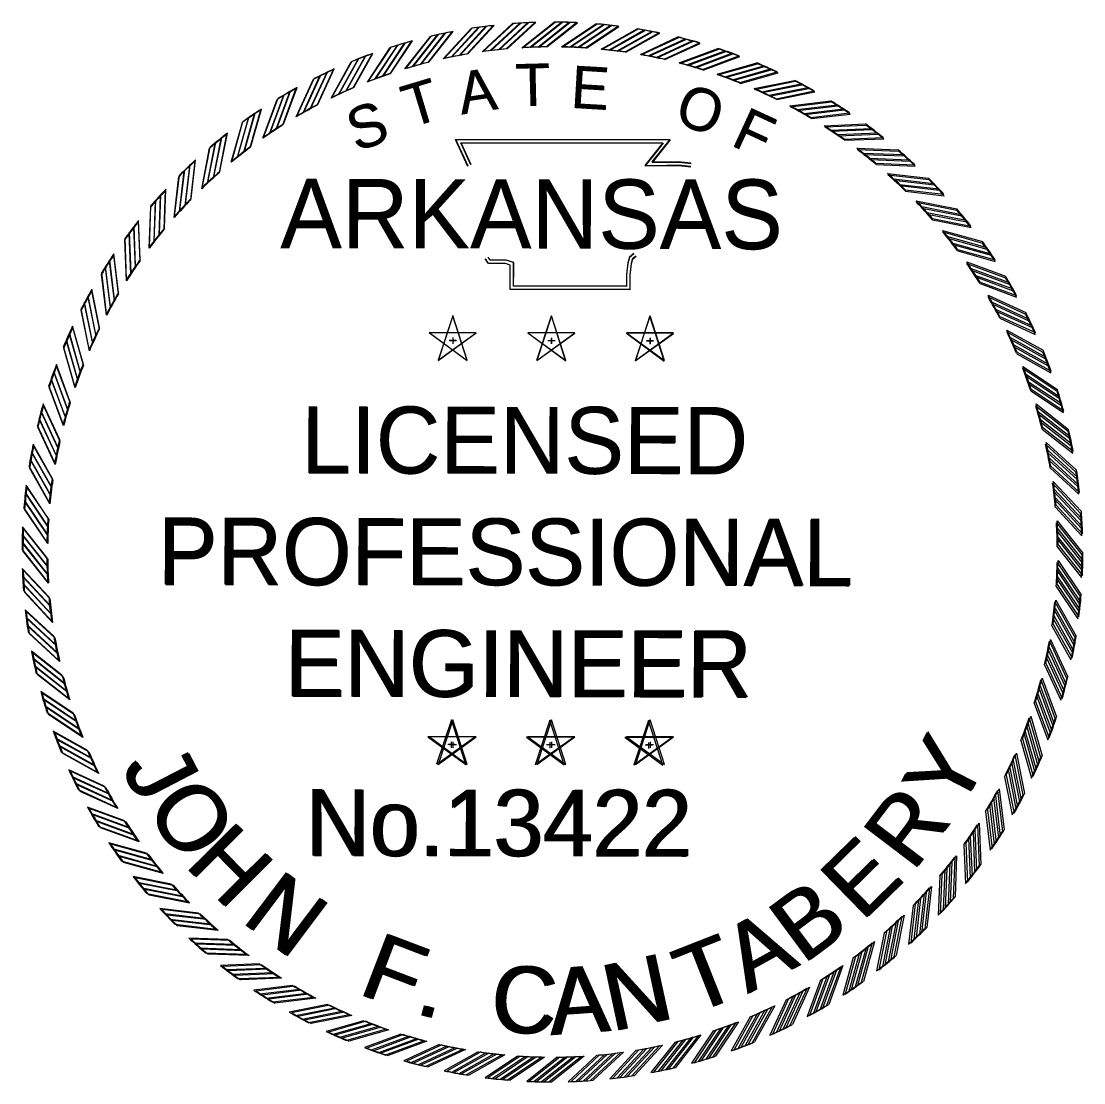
# Model space of a CAD drawing. Extents: x 1373884 to 1376992, y 1168426 to 1170473.
# Drawn here: x 1376555.8 to 1376796.3, y 1168433.2 to 1168673.5 of the extents above; entities that cross this region are included whole.
import ezdxf

# ---------------------------------------------------------------- set-up
doc = ezdxf.new("R2010")
doc.units = 0
doc.layers.add('Default', color=7, linetype='Continuous')
doc.layers.add('G-ANNO-STMP', color=7, linetype='Continuous')

# ---------------------------------------------------------------- blocks, each defined once
blk = doc.blocks.new('STAR')
at = {"layer": 'Default'}
for p, q in [((-0.0001, 0.0615), (-0.0366, -0.0504)), ((0.0362, -0.0503), (0, 0.0617)), ((0.0587, 0.0188), (-0.059, 0.0189)), ((-0.0589, 0.0188), (0.0363, -0.0505)), ((-0.0365, -0.0503), (0.0589, 0.0188)), ((-0.0085, 0), (0.009, 0)), ((0, 0.0063), (0, -0.0085))]:
    blk.add_line(p, q, dxfattribs=at)
blk = doc.blocks.new('RP')
at = {"layer": 'Default'}
for p, q in [((-0.0781, 1.2656), (0.003, 1.33)), ((-0.058, 1.2667), (0.0216, 1.3299)), ((-0.0375, 1.2674), (0.0405, 1.3294)), ((-0.0176, 1.2679), (0.059, 1.3287))]:
    blk.add_line(p, q, dxfattribs=at)
for radius, start, end in [(1.33, 87.4562, 89.8699), (1.268, 90.7933, 93.5307)]:
    blk.add_arc((0, 0), radius, start, end, dxfattribs=at)

msp = doc.modelspace()

# ---------------------------------------------------------------- linework, layer by layer
at = {"layer": 'G-ANNO-STMP'}
for points in [[(1376656.89, 1168640.66), (1376654.09, 1168646.73), (1376702.61, 1168646.76), (1376698.55, 1168641.66), (1376701.85, 1168641.71), (1376704.6, 1168641.74), (1376707.35, 1168641.44)], [(1376656.99, 1168640.69), (1376654.2, 1168646.77), (1376702.72, 1168646.63), (1376698.65, 1168641.55), (1376701.95, 1168641.59), (1376704.7, 1168641.61), (1376707.45, 1168641.3)], [(1376657.59, 1168640.98), (1376655.29, 1168645.96), (1376701.01, 1168645.99), (1376696.94, 1168640.87), (1376701.86, 1168640.94), (1376704.57, 1168640.97), (1376707.27, 1168640.68)], [(1376657.69, 1168641.01), (1376655.4, 1168646), (1376701.13, 1168645.87), (1376697.04, 1168640.77), (1376701.95, 1168640.82), (1376704.66, 1168640.84), (1376707.37, 1168640.54)], [(1376694.48, 1168620.92), (1376693.46, 1168620.09), (1376693.1, 1168618.79), (1376692.82, 1168616.17), (1376692.82, 1168613.54), (1376667.27, 1168613.54), (1376667.27, 1168617.3), (1376667.27, 1168618.88), (1376665.52, 1168619.41), (1376661.96, 1168619.41), (1376661.51, 1168620.11)], [(1376694.5, 1168620.82), (1376693.48, 1168620), (1376693.12, 1168618.7), (1376692.83, 1168616.08), (1376692.82, 1168613.45), (1376667.27, 1168613.54), (1376667.28, 1168617.3), (1376667.29, 1168618.87), (1376665.54, 1168619.42), (1376661.99, 1168619.43), (1376661.53, 1168620.13)], [(1376694.96, 1168620.32), (1376694.13, 1168619.65), (1376693.86, 1168618.64), (1376693.58, 1168616.13), (1376693.58, 1168612.77), (1376666.5, 1168612.77), (1376666.5, 1168617.3), (1376666.5, 1168618.31), (1376665.4, 1168618.64), (1376661.55, 1168618.64), (1376660.86, 1168619.69)], [(1376694.99, 1168620.23), (1376694.16, 1168619.56), (1376693.88, 1168618.55), (1376693.6, 1168616.04), (1376693.58, 1168612.68), (1376666.5, 1168612.77), (1376666.51, 1168617.3), (1376666.52, 1168618.31), (1376665.42, 1168618.65), (1376661.57, 1168618.66), (1376660.89, 1168619.71)]]:
    msp.add_lwpolyline(points, dxfattribs=at)

# ---------------------------------------------------------------- block references
for name, p, xscale, yscale, rotation in [('RP', (1376676.16, 1168553.35), 90.20715837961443, 90.20715837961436, 4.500000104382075), ('RP', (1376675.96, 1168553.32), 90.2071583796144, 90.20715837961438, 4.304199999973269), ('RP', (1376676.16, 1168553.35), 90.2071583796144, 90.20715837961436, 1.0438208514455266e-07), ('RP', (1376676.16, 1168553.35), 90.20715837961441, 90.20715837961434, -4.499999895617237), ('RP', (1376675.96, 1168553.32), 90.20715837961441, 90.20715837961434, -4.695800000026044), ('RP', (1376676.16, 1168553.35), 90.20715837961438, 90.20715837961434, 13.500000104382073), ('RP', (1376675.96, 1168553.32), 90.2071583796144, 90.20715837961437, 13.304199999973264), ('RP', (1376676.16, 1168553.35), 90.20715837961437, 90.20715837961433, 9.000000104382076), ('RP', (1376675.96, 1168553.32), 90.20715837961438, 90.20715837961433, 8.804199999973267), ('RP', (1376675.96, 1168553.32), 90.2071583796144, 90.20715837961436, -0.19580000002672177), ('RP', (1376676.16, 1168553.35), 90.20715837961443, 90.20715837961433, -8.999999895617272), ('RP', (1376675.96, 1168553.32), 90.20715837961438, 90.20715837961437, -9.19580000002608), ('RP', (1376676.16, 1168553.35), 90.20715837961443, 90.20715837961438, -13.499999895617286), ('RP', (1376675.96, 1168553.32), 90.20715837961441, 90.20715837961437, -13.695800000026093), ('RP', (1376676.16, 1168553.35), 90.20715837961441, 90.20715837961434, 18.00000010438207), ('RP', (1376675.96, 1168553.32), 90.2071583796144, 90.20715837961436, 17.804199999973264), ('RP', (1376676.16, 1168553.35), 90.20715837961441, 90.20715837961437, -17.999999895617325), ('RP', (1376675.96, 1168553.32), 90.2071583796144, 90.20715837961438, -18.19580000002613), ('RP', (1376676.16, 1168553.35), 90.2071583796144, 90.20715837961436, 22.500000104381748), ('RP', (1376675.96, 1168553.32), 90.2071583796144, 90.20715837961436, 22.304199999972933), ('RP', (1376676.16, 1168553.35), 90.20715837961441, 90.20715837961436, -22.499999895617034), ('RP', (1376675.96, 1168553.32), 90.20715837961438, 90.20715837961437, -22.695800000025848), ('RP', (1376676.16, 1168553.35), 90.2071583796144, 90.20715837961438, 27.000000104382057), ('RP', (1376675.96, 1168553.32), 90.2071583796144, 90.20715837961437, 26.80419999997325), ('RP', (1376676.16, 1168553.35), 90.20715837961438, 90.20715837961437, -26.999999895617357), ('RP', (1376675.96, 1168553.32), 90.2071583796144, 90.20715837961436, -27.19580000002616), ('RP', (1376676.16, 1168553.35), 90.20715837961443, 90.2071583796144, -31.49999989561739), ('RP', (1376675.96, 1168553.32), 90.20715837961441, 90.2071583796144, -31.695800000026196), ('RP', (1376676.16, 1168553.35), 90.20715837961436, 90.20715837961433, 31.50000010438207), ('RP', (1376675.96, 1168553.32), 90.20715837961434, 90.20715837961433, 31.30419999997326), ('RP', (1376676.16, 1168553.35), 90.20715837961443, 90.20715837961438, -35.999999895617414), ('RP', (1376675.96, 1168553.32), 90.2071583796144, 90.20715837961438, -36.195800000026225), ('RP', (1376676.16, 1168553.35), 90.20715837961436, 90.20715837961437, 36.00000010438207), ('RP', (1376675.96, 1168553.32), 90.20715837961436, 90.20715837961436, 35.804199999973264), ('RP', (1376676.16, 1168553.35), 90.20715837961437, 90.20715837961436, 40.50000010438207), ('RP', (1376675.96, 1168553.32), 90.20715837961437, 90.20715837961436, 40.30419999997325), ('RP', (1376676.16, 1168553.35), 90.2071583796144, 90.2071583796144, -40.49999989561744), ('RP', (1376675.96, 1168553.32), 90.2071583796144, 90.20715837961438, -40.69580000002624), ('RP', (1376675.96, 1168553.32), 90.20715837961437, 90.20715837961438, 44.80419999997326), ('RP', (1376676.16, 1168553.35), 90.2071583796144, 90.20715837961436, -44.99999989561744), ('RP', (1376675.96, 1168553.32), 90.20715837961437, 90.20715837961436, -45.19580000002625), ('RP', (1376676.16, 1168553.35), 90.20715837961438, 90.20715837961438, 45.00000010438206), ('RP', (1376676.16, 1168553.35), 90.20715837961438, 90.20715837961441, 49.500000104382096), ('RP', (1376675.96, 1168553.32), 90.20715837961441, 90.2071583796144, 49.304199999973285), ('RP', (1376676.16, 1168553.35), 90.20715837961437, 90.20715837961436, -49.499999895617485), ('RP', (1376675.96, 1168553.32), 90.20715837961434, 90.20715837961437, -49.695800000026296), ('RP', (1376676.16, 1168553.35), 90.20715837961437, 90.20715837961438, 54.00000010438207), ('RP', (1376675.96, 1168553.32), 90.20715837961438, 90.20715837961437, 53.804199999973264), ('RP', (1376676.16, 1168553.35), 90.20715837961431, 90.20715837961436, -53.999999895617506), ('RP', (1376675.96, 1168553.32), 90.20715837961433, 90.20715837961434, -54.1958000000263), ('RP', (1376675.96, 1168553.32), 90.20715837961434, 90.20715837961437, 58.304199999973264), ('RP', (1376676.16, 1168553.35), 90.20715837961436, 90.20715837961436, 58.50000010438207), ('RP', (1376676.16, 1168553.35), 90.20715837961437, 90.20715837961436, -58.49999989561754), ('RP', (1376675.96, 1168553.32), 90.20715837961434, 90.20715837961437, -58.695800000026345), ('RP', (1376675.96, 1168553.32), 90.20715837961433, 90.20715837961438, -63.19580000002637), ('RP', (1376676.16, 1168553.35), 90.20715837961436, 90.20715837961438, -62.99999989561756), ('RP', (1376675.96, 1168553.32), 90.20715837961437, 90.20715837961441, 62.804199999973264), ('RP', (1376676.16, 1168553.35), 90.20715837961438, 90.2071583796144, 63.000000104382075), ('STAR', (1376653.47, 1168601.3), 90.2071583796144, 90.20715837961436, -0.19580000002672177), ('STAR', (1376653.51, 1168601.25), 90.2071583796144, 90.20715837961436, 1.0438208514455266e-07), ('STAR', (1376675.79, 1168601.22), 90.2071583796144, 90.20715837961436, -0.19580000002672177), ('STAR', (1376675.83, 1168601.25), 90.2071583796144, 90.20715837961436, 1.0438208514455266e-07), ('STAR', (1376698.1, 1168601.14), 90.2071583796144, 90.20715837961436, -0.19580000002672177), ('STAR', (1376698.14, 1168601.25), 90.2071583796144, 90.20715837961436, 1.0438208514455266e-07), ('RP', (1376675.96, 1168553.32), 90.20715837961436, 90.2071583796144, 67.30419999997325), ('RP', (1376676.16, 1168553.35), 90.20715837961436, 90.20715837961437, 67.50000010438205), ('RP', (1376675.96, 1168553.32), 90.20715837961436, 90.20715837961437, -67.69580000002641), ('RP', (1376676.16, 1168553.35), 90.20715837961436, 90.2071583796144, -67.49999989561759), ('RP', (1376675.96, 1168553.32), 90.20715837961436, 90.2071583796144, -72.19580000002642), ('RP', (1376676.16, 1168553.35), 90.20715837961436, 90.2071583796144, -71.99999989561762), ('RP', (1376675.96, 1168553.32), 90.20715837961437, 90.2071583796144, 71.80419999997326), ('RP', (1376676.16, 1168553.35), 90.20715837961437, 90.20715837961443, 72.00000010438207), ('RP', (1376675.96, 1168553.32), 90.20715837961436, 90.2071583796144, 76.30419999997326), ('RP', (1376675.96, 1168553.32), 90.20715837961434, 90.20715837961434, -76.69580000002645), ('RP', (1376676.16, 1168553.35), 90.20715837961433, 90.20715837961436, -76.49999989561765), ('RP', (1376676.16, 1168553.35), 90.20715837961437, 90.20715837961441, 76.50000010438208), ('RP', (1376675.96, 1168553.32), 90.20715837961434, 90.20715837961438, 80.80419999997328), ('RP', (1376676.16, 1168553.35), 90.20715837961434, 90.20715837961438, 81.0000001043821), ('RP', (1376675.96, 1168553.32), 90.20715837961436, 90.2071583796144, -81.19580000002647), ('RP', (1376676.16, 1168553.35), 90.20715837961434, 90.2071583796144, -80.99999989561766), ('RP', (1376675.96, 1168553.32), 90.20715837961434, 90.20715837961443, 85.30419999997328), ('RP', (1376676.16, 1168553.35), 90.20715837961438, 90.2071583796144, 85.50000010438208), ('RP', (1376675.96, 1168553.32), 90.20715837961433, 90.20715837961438, -85.69580000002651), ('RP', (1376676.16, 1168553.35), 90.20715837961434, 90.20715837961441, -85.49999989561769), ('RP', (1376676.16, 1168553.35), 90.20715837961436, 90.20715837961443, -89.99999989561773), ('RP', (1376675.96, 1168553.32), 90.20715837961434, 90.20715837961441, 89.80419999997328), ('RP', (1376676.16, 1168553.35), 90.20715837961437, 90.20715837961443, 90.0000001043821), ('RP', (1376675.96, 1168553.32), 90.20715837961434, 90.20715837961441, -90.19580000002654), ('RP', (1376675.96, 1168553.32), 90.20715837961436, 90.20715837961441, -94.69580000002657), ('RP', (1376676.16, 1168553.35), 90.20715837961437, 90.20715837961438, -94.49999989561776), ('RP', (1376675.96, 1168553.32), 90.20715837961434, 90.20715837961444, 94.30419999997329), ('RP', (1376676.16, 1168553.35), 90.20715837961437, 90.20715837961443, 94.5000001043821), ('RP', (1376675.96, 1168553.32), 90.20715837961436, 90.20715837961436, 98.8041999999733), ('RP', (1376675.96, 1168553.32), 90.20715837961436, 90.2071583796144, -99.19580000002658), ('RP', (1376676.16, 1168553.35), 90.20715837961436, 90.2071583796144, -98.99999989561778), ('RP', (1376676.16, 1168553.35), 90.20715837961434, 90.20715837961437, 99.0000001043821), ('RP', (1376675.96, 1168553.32), 90.20715837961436, 90.2071583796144, 103.30419999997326), ('RP', (1376676.16, 1168553.35), 90.20715837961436, 90.2071583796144, 103.50000010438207), ('RP', (1376675.96, 1168553.32), 90.20715837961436, 90.2071583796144, -103.69580000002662), ('RP', (1376676.16, 1168553.35), 90.20715837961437, 90.20715837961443, -103.4999998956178), ('RP', (1376675.96, 1168553.32), 90.20715837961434, 90.2071583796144, -108.19580000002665), ('RP', (1376676.16, 1168553.35), 90.20715837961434, 90.2071583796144, -107.99999989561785), ('RP', (1376675.96, 1168553.32), 90.20715837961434, 90.20715837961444, 107.80419999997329), ('RP', (1376676.16, 1168553.35), 90.20715837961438, 90.20715837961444, 108.0000001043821), ('RP', (1376675.96, 1168553.32), 90.20715837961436, 90.20715837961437, 112.30419999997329), ('STAR', (1376653.16, 1168509.8), 90.2071583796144, 90.20715837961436, -0.19580000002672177), ('STAR', (1376653.51, 1168509.76), 90.2071583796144, 90.20715837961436, 1.0438208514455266e-07), ('STAR', (1376675.48, 1168509.72), 90.2071583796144, 90.20715837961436, -0.19580000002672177), ('STAR', (1376675.83, 1168509.76), 90.2071583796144, 90.20715837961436, 1.0438208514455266e-07), ('STAR', (1376697.79, 1168509.65), 90.2071583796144, 90.20715837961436, -0.19580000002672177), ('STAR', (1376698.14, 1168509.76), 90.2071583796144, 90.20715837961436, 1.0438208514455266e-07), ('RP', (1376675.96, 1168553.32), 90.20715837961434, 90.20715837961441, -112.69580000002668), ('RP', (1376676.16, 1168553.35), 90.20715837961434, 90.20715837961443, -112.49999989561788), ('RP', (1376676.16, 1168553.35), 90.20715837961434, 90.2071583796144, 112.5000001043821), ('RP', (1376675.96, 1168553.32), 90.20715837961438, 90.20715837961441, -117.19580000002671), ('RP', (1376676.16, 1168553.35), 90.2071583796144, 90.20715837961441, -116.9999998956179), ('RP', (1376675.96, 1168553.32), 90.20715837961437, 90.2071583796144, 116.80419999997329), ('RP', (1376676.16, 1168553.35), 90.20715837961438, 90.2071583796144, 117.0000001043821), ('RP', (1376675.96, 1168553.32), 90.20715837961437, 90.20715837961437, 121.30419999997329), ('RP', (1376676.16, 1168553.35), 90.20715837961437, 90.20715837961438, 121.5000001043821), ('RP', (1376675.96, 1168553.32), 90.20715837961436, 90.20715837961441, -121.69580000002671), ('RP', (1376676.16, 1168553.35), 90.20715837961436, 90.20715837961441, -121.4999998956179), ('RP', (1376675.96, 1168553.32), 90.20715837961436, 90.20715837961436, 125.80419999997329), ('RP', (1376676.16, 1168553.35), 90.20715837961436, 90.20715837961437, 126.00000010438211), ('RP', (1376675.96, 1168553.32), 90.20715837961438, 90.2071583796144, -126.19580000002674), ('RP', (1376676.16, 1168553.35), 90.20715837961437, 90.20715837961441, -125.99999989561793), ('RP', (1376675.96, 1168553.32), 90.20715837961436, 90.20715837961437, 130.3041999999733), ('RP', (1376675.96, 1168553.32), 90.20715837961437, 90.20715837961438, -130.6958000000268), ('RP', (1376676.16, 1168553.35), 90.20715837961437, 90.20715837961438, -130.49999989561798), ('RP', (1376676.16, 1168553.35), 90.20715837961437, 90.20715837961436, 130.50000010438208), ('RP', (1376675.96, 1168553.32), 90.20715837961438, 90.20715837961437, 134.80419999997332), ('RP', (1376676.16, 1168553.35), 90.2071583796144, 90.20715837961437, 135.00000010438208), ('RP', (1376675.96, 1168553.32), 90.20715837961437, 90.20715837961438, -135.19580000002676), ('RP', (1376676.16, 1168553.35), 90.20715837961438, 90.20715837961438, -134.99999989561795), ('RP', (1376675.96, 1168553.32), 90.20715837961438, 90.20715837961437, 139.30419999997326), ('RP', (1376676.16, 1168553.35), 90.20715837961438, 90.20715837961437, 139.50000010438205), ('RP', (1376675.96, 1168553.32), 90.20715837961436, 90.20715837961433, -139.69580000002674), ('RP', (1376676.16, 1168553.35), 90.20715837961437, 90.20715837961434, -139.49999989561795), ('RP', (1376675.96, 1168553.32), 90.20715837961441, 90.20715837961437, 143.8041999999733), ('RP', (1376676.16, 1168553.35), 90.20715837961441, 90.20715837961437, 144.00000010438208), ('RP', (1376675.96, 1168553.32), 90.20715837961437, 90.20715837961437, -144.19580000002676), ('RP', (1376676.16, 1168553.35), 90.2071583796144, 90.20715837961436, -143.99999989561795), ('RP', (1376675.96, 1168553.32), 90.20715837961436, 90.20715837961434, -148.69580000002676), ('RP', (1376676.16, 1168553.35), 90.20715837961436, 90.20715837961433, -148.49999989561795), ('RP', (1376675.96, 1168553.32), 90.20715837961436, 90.20715837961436, 148.3041999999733), ('RP', (1376676.16, 1168553.35), 90.20715837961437, 90.20715837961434, 148.50000010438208), ('RP', (1376675.96, 1168553.32), 90.20715837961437, 90.20715837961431, -153.1958000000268), ('RP', (1376676.16, 1168553.35), 90.20715837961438, 90.20715837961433, -152.99999989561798), ('RP', (1376675.96, 1168553.32), 90.20715837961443, 90.20715837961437, 152.8041999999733), ('RP', (1376676.16, 1168553.35), 90.20715837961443, 90.2071583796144, 153.00000010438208), ('RP', (1376675.96, 1168553.32), 90.2071583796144, 90.20715837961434, 157.3041999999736), ('RP', (1376676.16, 1168553.35), 90.20715837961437, 90.20715837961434, 157.50000010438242), ('RP', (1376675.96, 1168553.32), 90.2071583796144, 90.20715837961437, -157.6958000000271), ('RP', (1376676.16, 1168553.35), 90.20715837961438, 90.20715837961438, -157.4999998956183), ('RP', (1376675.96, 1168553.32), 90.20715837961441, 90.20715837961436, 161.8041999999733), ('RP', (1376676.16, 1168553.35), 90.20715837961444, 90.20715837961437, 162.00000010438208), ('RP', (1376675.96, 1168553.32), 90.2071583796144, 90.20715837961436, -162.19580000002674), ('RP', (1376676.16, 1168553.35), 90.20715837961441, 90.20715837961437, -161.99999989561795), ('RP', (1376675.96, 1168553.32), 90.20715837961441, 90.20715837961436, 166.3041999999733), ('RP', (1376676.16, 1168553.35), 90.20715837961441, 90.20715837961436, 166.50000010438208), ('RP', (1376675.96, 1168553.32), 90.2071583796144, 90.20715837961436, -166.69580000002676), ('RP', (1376676.16, 1168553.35), 90.20715837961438, 90.20715837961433, -166.49999989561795), ('RP', (1376675.96, 1168553.32), 90.2071583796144, 90.20715837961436, 170.8041999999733), ('RP', (1376676.16, 1168553.35), 90.2071583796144, 90.20715837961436, 171.00000010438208), ('RP', (1376676.16, 1168553.35), 90.2071583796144, 90.20715837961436, -175.49999989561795), ('RP', (1376675.96, 1168553.32), 90.20715837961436, 90.20715837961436, -171.19580000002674), ('RP', (1376676.16, 1168553.35), 90.20715837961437, 90.20715837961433, -170.99999989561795), ('RP', (1376675.96, 1168553.32), 90.20715837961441, 90.20715837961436, 175.3041999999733), ('RP', (1376676.16, 1168553.35), 90.20715837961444, 90.20715837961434, 175.50000010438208), ('RP', (1376675.96, 1168553.32), 90.2071583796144, 90.20715837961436, 179.8041999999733), ('RP', (1376676.16, 1168553.35), 90.20715837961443, 90.20715837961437, -179.99999989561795), ('RP', (1376675.96, 1168553.32), 90.20715837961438, 90.20715837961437, -175.69580000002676)]:
    msp.add_blockref(name, p, dxfattribs=dict(at, xscale=xscale, yscale=yscale, rotation=rotation))

# ---------------------------------------------------------------- texts
for s, height, rotation, p in [('T', 9.57, 1.4789, (1376667.77, 1168654.24)), ('T', 9.57, 1.2831, (1376667.91, 1168654.24)), ('A', 9.57, 8.6788, (1376655.41, 1168652.34)), ('A', 9.57, 8.483, (1376655.55, 1168652.37)), ('E', 9.57, 356.672, (1376680.02, 1168653.95)), ('E', 9.57, 356.4762, (1376680.16, 1168653.9)), ('T', 9.57, 16.9015, (1376643.79, 1168649.3)), ('T', 9.57, 16.7057, (1376643.92, 1168649.38)), ('O', 9.57, 341.2218, (1376703.26, 1168650.67)), ('O', 9.57, 341.026, (1376703.39, 1168650.54)), ('S', 9.57, 19.7726, (1376631.62, 1168643.84)), ('S', 9.57, 19.5768, (1376631.73, 1168643.96)), ('F', 9.57, 335.3628, (1376716.16, 1168645.62)), ('F', 9.57, 335.167, (1376716.27, 1168645.45)), ('ARKANSAS', 15.621, 0, (1376614.42, 1168622.07)), ('ARKANSAS', 15.621, 359.8042, (1376614.46, 1168622.25)), ('LICENSED', 15.122, 359.8042, (1376619.13, 1168571.24)), ('LICENSED', 15.122, 0, (1376619.27, 1168571.08)), ('PROFESSIONAL', 15.1223, 359.8042, (1376586.64, 1168546.06)), ('PROFESSIONAL', 15.1223, 0, (1376586.87, 1168545.79)), ('ENGINEER', 15.122, 359.8042, (1376615.36, 1168520.67)), ('ENGINEER', 15.122, 0, (1376615.67, 1168520.5)), ('Y', 15.12, 62.5392, (1376768.15, 1168493.97)), ('Y', 15.12, 62.735, (1376768.55, 1168494.32)), ('J', 15.12, 297.2813, (1376578.21, 1168504.71)), ('J', 15.12, 297.4771, (1376578.58, 1168504.41)), ('O', 15.12, 304.1899, (1376583.57, 1168495.44)), ('O', 15.12, 304.3857, (1376583.97, 1168495.16)), ('No.13422', 15.063, 359.8042, (1376620.01, 1168484.61)), ('No.13422', 15.063, 0, (1376620.45, 1168484.45)), ('R', 15.12, 52.7437, (1376757.59, 1168480.65)), ('R', 15.12, 52.9395, (1376758.04, 1168480.97)), ('H', 15.12, 314.7447, (1376592.49, 1168482.41)), ('H', 15.12, 314.9405, (1376592.93, 1168482.16)), ('E', 15.12, 44.306, (1376746.07, 1168469.4)), ('E', 15.12, 44.5018, (1376746.56, 1168469.67)), ('N', 15.12, 322.9417, (1376605.26, 1168469.77)), ('N', 15.12, 323.1375, (1376605.74, 1168469.56)), ('B', 15.12, 36.505, (1376732.72, 1168459.77)), ('B', 15.12, 36.7008, (1376733.25, 1168460)), ('A', 15.12, 28.8562, (1376720.16, 1168453.18)), ('A', 15.12, 29.052, (1376720.71, 1168453.36)), ('F', 15.12, 339.0288, (1376631.65, 1168453.39)), ('F', 15.12, 339.2246, (1376632.2, 1168453.27)), ('T', 15.12, 21.4329, (1376707.59, 1168448.44)), ('T', 15.12, 21.6287, (1376708.15, 1168448.59)), ('N', 15.12, 12.0703, (1376689.35, 1168444.67)), ('N', 15.12, 12.2661, (1376689.92, 1168444.75)), ('C', 15.12, 356.1028, (1376661.66, 1168444.9)), ('C', 15.12, 356.2986, (1376662.23, 1168444.89)), ('A', 15.12, 3.9092, (1376675.53, 1168443.9)), ('A', 15.12, 4.105, (1376676.1, 1168443.93)), ('.', 15.12, 344.7037, (1376644.55, 1168448.92)), ('.', 15.12, 344.8995, (1376645.11, 1168448.84))]:
    msp.add_text(s, height=height, rotation=rotation, dxfattribs=at).set_placement(p)

doc.saveas('drawing.dxf')
